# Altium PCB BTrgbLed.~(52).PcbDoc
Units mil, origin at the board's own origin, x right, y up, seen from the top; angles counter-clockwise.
Board outline 3886.28 x 3884.79 mil, 2 copper layers (Top Layer, Bottom Layer); 1 components, 12 nets, 2 pads, 4 vias.
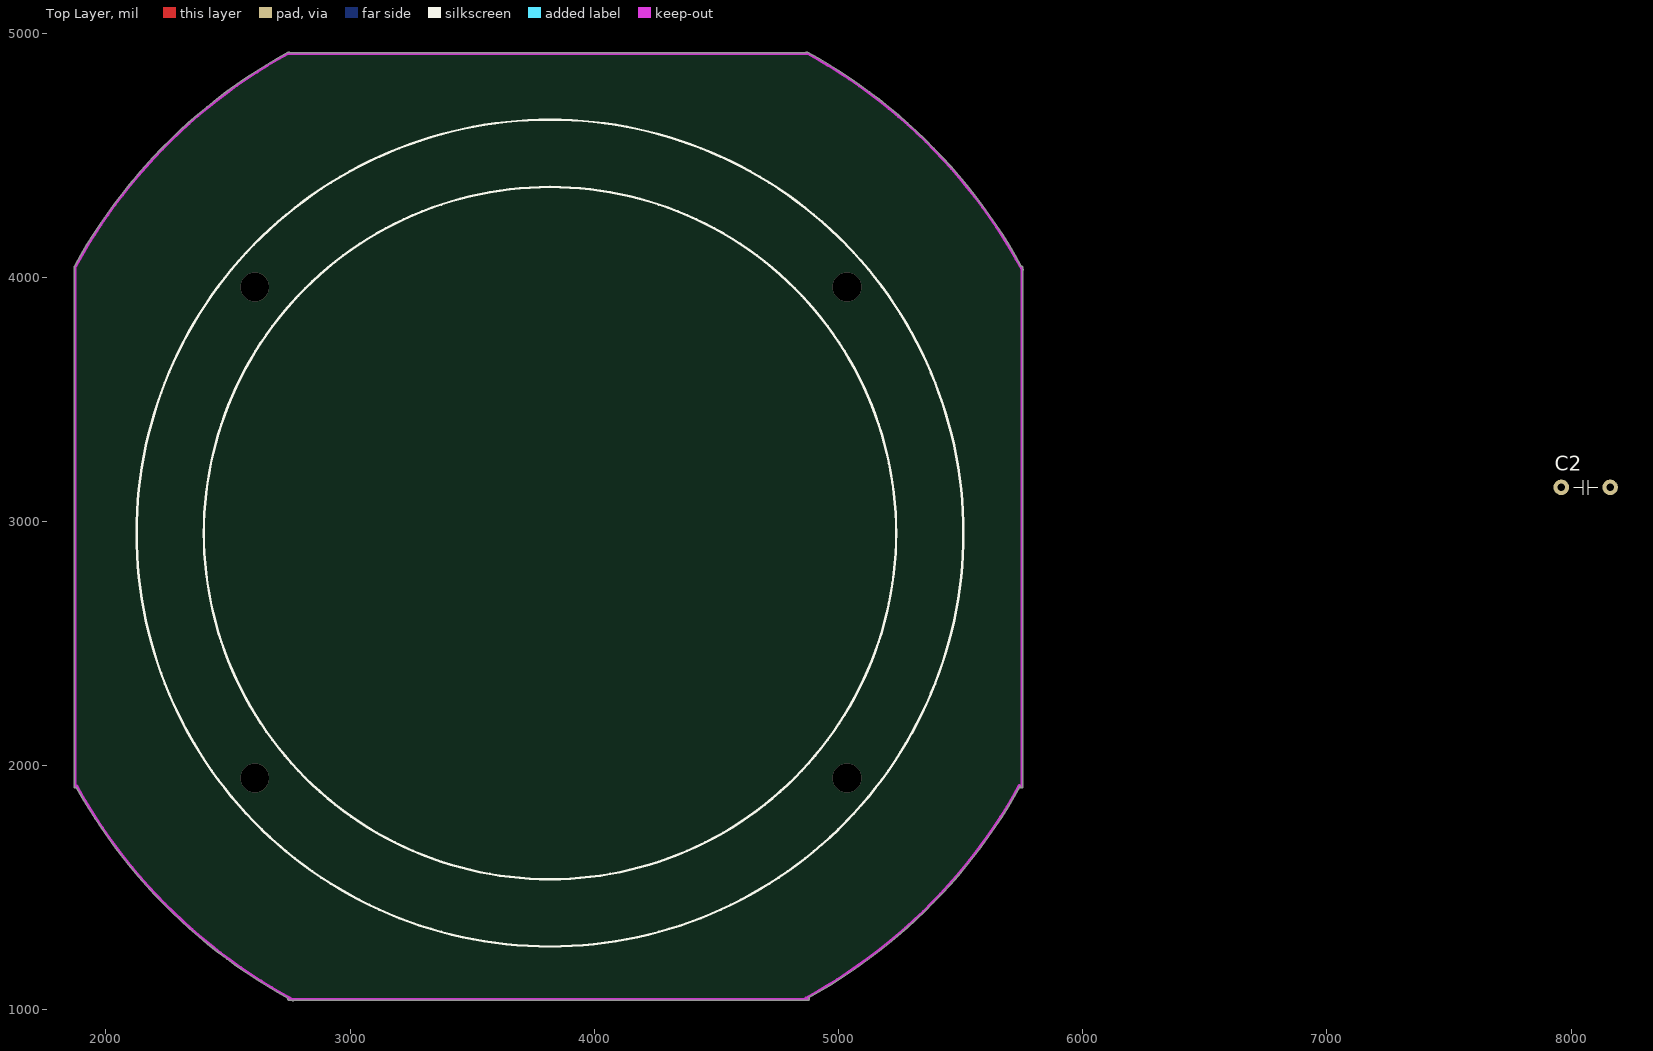
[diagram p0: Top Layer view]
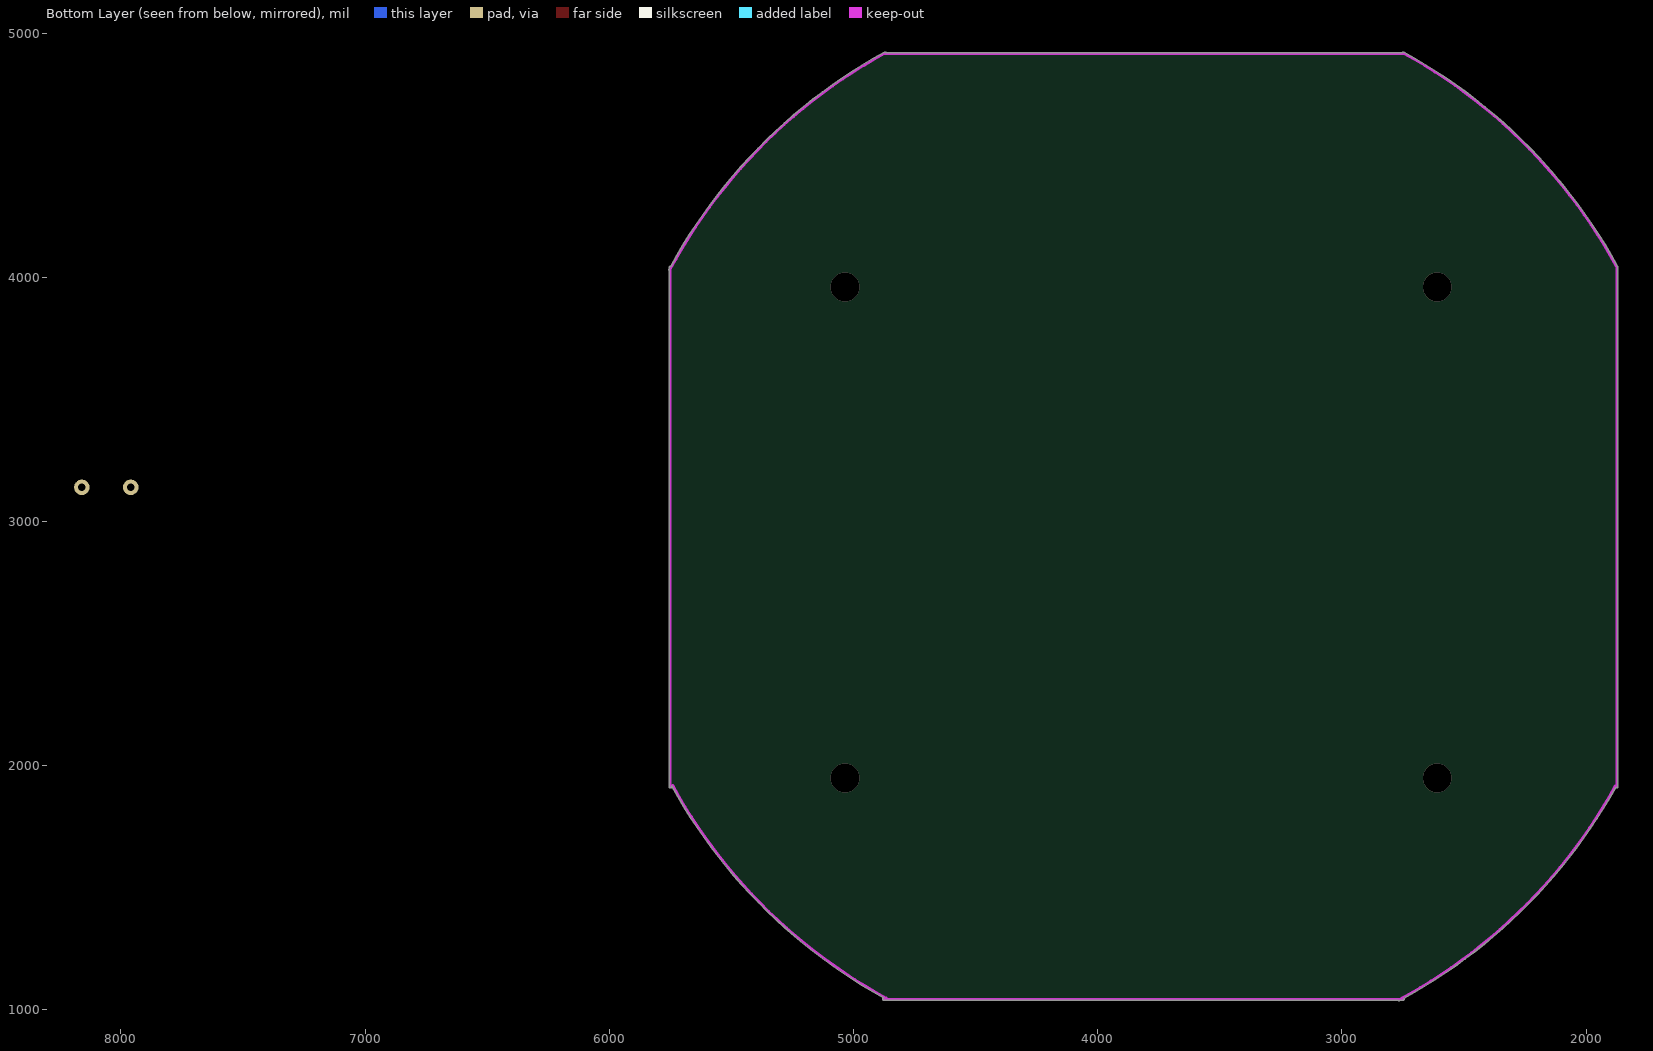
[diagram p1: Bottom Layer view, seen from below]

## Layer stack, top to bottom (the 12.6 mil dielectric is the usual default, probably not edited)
Top Layer: signal copper 1.4
Dielectric: dielectric 12.6, FR-4, Dk 4.8
Bottom Layer: signal copper 1.4

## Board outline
2750,1039.98 2761.53,1039.98 ccw(c3810.28,2985) 2764.5,1038.38 ccw(c2766.88,1042.8) 2771.03,1039.98 4875.98,1039.98 ccw(c4875.98,1045) 4881,1045 ccw(c4875.98,1045) 4877.16,1049.88 ccw(c3810.28,2985) 5744.74,1916.92 ccw(c5740.35,1919.34) 5744.98,1917.43 5744.98,1914.02 ccw(c5750,1914.02) 5755.02,1914.02 5755.02,4027.36 ccw(c5751.25,4030.67) 5756.26,4030.67 ccw(c5751.25,4030.67) 5755.66,4033.05 ccw(c3810.28,2985) 5755.02,4034.26 5755.02,4040 ccw(c5750,4040) 5749.21,4044.95 ccw(c3810.28,2985) 4873.82,4921.96 ccw(c4871.41,4917.56) 4867.03,4920.02 2752.96,4920.02 ccw(c2748.72,4917.33) 2746.3,4921.73 ccw(c3810.28,2985) 1872.41,4046.9 ccw(c1876.81,4044.49) 1871.83,4043.89 ccw(c1875,4040) 1869.98,4040 1869.98,1914.02 ccw(c1875,1914.02) 1879.06,1911.07 ccw(c3810.28,2985) 2746.23,1048.31 ccw(c2750,1045)

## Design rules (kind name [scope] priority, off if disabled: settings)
Clearance çE»É¦w¥þ¶¡¶Z [All] p1: gap=25
Clearance [All] p2: gap=10
PolygonConnect [All] p1: connectstyle=Relief reliefconductorwidth=10 reliefentries=4 polygonreliefangle="90 Angle"
RoutingLayers [All] p1: top layer_v5=FALSE bottom layer_v5=TRUE
RoutingVias [All] p1: holewidth=28 width=50 viastyle="Through Hole" minholewidth=28 minwidth=50 maxholewidth=28 maxwidth=50
SilkscreenOverComponentPads [All] p1: minsilkscreentomaskgap=10
SolderMaskExpansion [All] p1: expansion=4
Width [All] p1: maxlimit=40 minlimit=20 preferedwidth=30
26 further rules are at their usual default settings.

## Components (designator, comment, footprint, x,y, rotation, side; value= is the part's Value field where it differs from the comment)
C2 "22pF" C200 8060,3140 r90 top

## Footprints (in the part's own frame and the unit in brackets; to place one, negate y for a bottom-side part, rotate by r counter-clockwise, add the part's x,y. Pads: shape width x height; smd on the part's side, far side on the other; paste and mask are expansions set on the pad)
C200 [mil] "鹅溅筿甧竟"
  round 64 hole 31.5: 1(0,100) 2(0,-100)
  silkscreen extent -30,-50 30,50, body extent -41,-136 39,135, height 354

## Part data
C2: library part Cap, "Capacitor"

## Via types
v1: diameter 118.11, hole 118.11, Top Layer to Bottom Layer, 4 vias

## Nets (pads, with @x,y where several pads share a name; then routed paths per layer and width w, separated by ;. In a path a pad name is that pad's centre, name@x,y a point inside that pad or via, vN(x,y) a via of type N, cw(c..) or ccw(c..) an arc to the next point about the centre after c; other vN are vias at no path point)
DI: 
DO: 
GND: 
NetC1_1: 
NetC2_2: C2.2
NetC3_2: 
NetDS1_1: 
NetIC1_3: 
NetR2_2: 
RX: 
TX: 
VCC: 
pads on no net: C2.1
copper on no net:
  other v1: 2610,1950 5035,1950 2610,3960 5035,3960

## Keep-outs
Keep-Out Layer:
  lines w10: 1875,1914.02 1875,4040 ; 1876.81,4044.49 cw(c3810.28,2985) 2748.72,4917.33 ; 1881.24,1917.47 ccw(c3810.28,2985) 2766.88,1042.8 ; 2750,1045 4875.98,1045 ; 2750,4915 4875.98,4915 ; 4865.51,1049.21 ccw(c3810.28,2985) 5740.35,1919.34 ; 4871.41,4917.56 cw(c3810.28,2985) 5751.25,4030.67 ; 5750,1914.02 5750,4040

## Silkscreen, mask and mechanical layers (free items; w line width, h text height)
Top Overlay:
  circle w10: c3818.9,2952.76 r1417.32
  circle w10: c3818.9,2952.76 r1692.91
